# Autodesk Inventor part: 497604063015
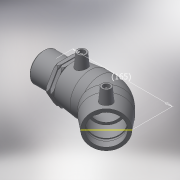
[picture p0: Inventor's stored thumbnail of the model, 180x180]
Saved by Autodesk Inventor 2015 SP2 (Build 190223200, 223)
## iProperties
Created: 2017-06
Part Number: 497604063015
Material: Generic
Description: PLASSON PE MALE TRANSITION 45° ELBOW 63-1.1/2"
Document SubType Name: Modeling
Designer: KIM
Mass: 55.0731 g
Surface Area: 148.067 cm^2
Volume: 55.0731 cm^3
Density: 1 g/cm^3
Appearance: Default
Author: KIM
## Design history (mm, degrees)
derived "497604.ipt"
feature "Solid1::497604.ipt"
tag "TaggingFeature1"
body "Solid1"
other parameters: "d2" = 82, "d4" = 33.75, "d5" = 73.8, "d8" = 168 deg, "d11" = 6.66667, "d29" = 59, "d30" = 15, "d31" = 47.25, "d34" = 5 deg, "d41" = 4, "d42" = 14, "d43" = 0, "d49" = 63, "d50" = 53.55, "d52" = 49.9, "d54" = 135 deg, "d86" = 36.9, "d87" = 135 deg, "d88" = 135, "d91" = 0, "d93" = 0, "d101" = 3, "d102" = 0, "d107" = 0.1, "d108" = 48, "d109" = 47.803, "d110" = 57, "d111" = 14.25, "d112" = 82, "d113" = 33.4621, "d114" = 51.3, "d116" = 2.46, "d122" = 0, "d123" = 2.39015, "d126" = 1.425, "d127" = 6.4125, "d128" = 82, "d131" = 63, "d_" = 63, "L_" = 192, "D_" = 48, "A_" = 59, "d_2" = 12, "L_1" = 57, "R_" = 47.803, "D_1" = 82, "d129" = 192
